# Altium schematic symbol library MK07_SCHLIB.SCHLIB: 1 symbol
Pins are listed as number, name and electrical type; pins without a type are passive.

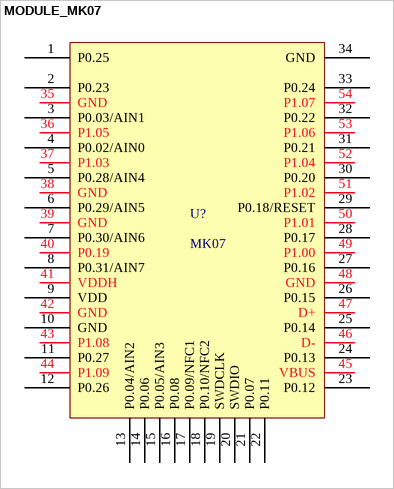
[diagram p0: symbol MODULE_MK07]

## MODULE_MK07
designator U?, comment MK07
footprint PCB_MK07 (21*13.8mm)
pins: 1 P0.25, 2 P0.23, 3 P0.03/AIN1, 4 P0.02/AIN0, 5 P0.28/AIN4, 6 P0.29/AIN5, 7 P0.30/AIN6, 8 P0.31/AIN7, 9 VDD, 10 GND, 11 P0.27, 12 P0.26, 13 P0.04/AIN2, 14 P0.06, 15 P0.05/AIN3, 16 P0.08, 17 P0.09/NFC1, 18 P0.10/NFC2, 19 SWDCLK, 20 SWDIO, 21 P0.07, 22 P0.11, 23 P0.12, 24 P0.13, 25 P0.14, 26 P0.15, 27 P0.16, 28 P0.17, 29 P0.18/RESET, 30 P0.20, 31 P0.21, 32 P0.22, 33 P0.24, 34 GND, 35 GND, 36 P1.05, 37 P1.03, 38 GND, 39 GND, 40 P0.19, 41 VDDH, 42 GND, 43 P1.08, 44 P1.09, 45 VBUS, 46 D-, 47 D+, 48 GND, 49 P1.00, 50 P1.01, 51 P1.02, 52 P1.04, 53 P1.06, 54 P1.07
